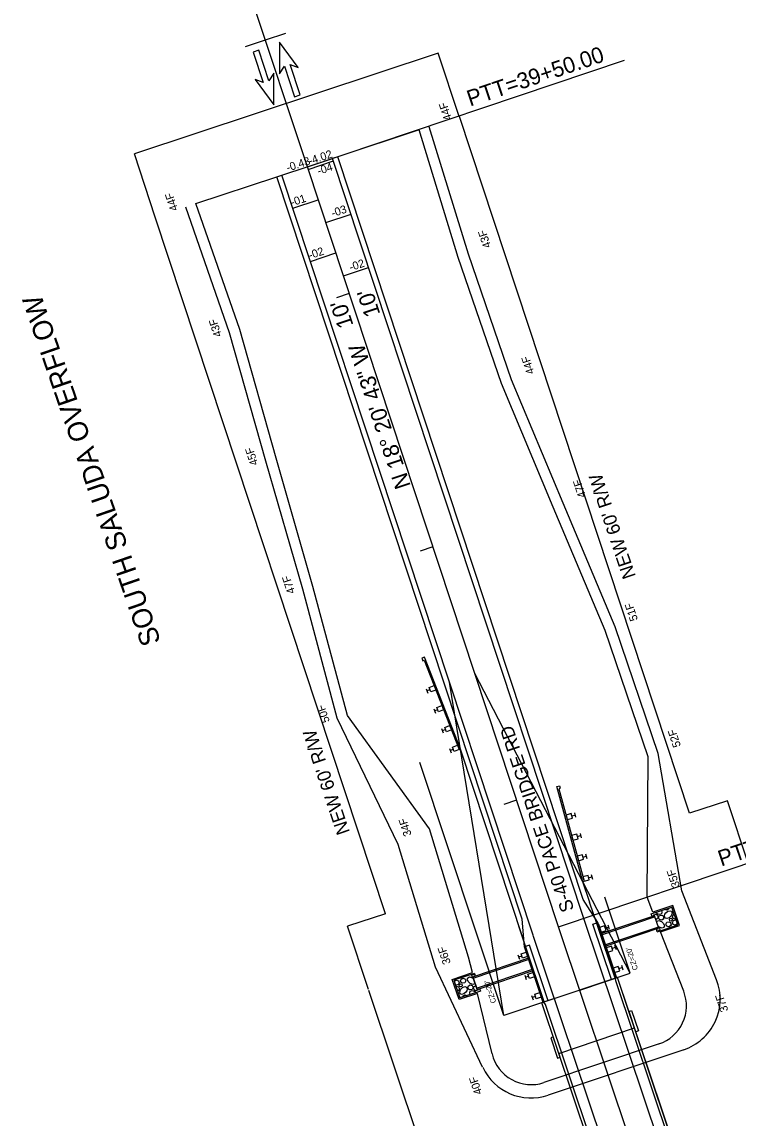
# Model space of a CAD drawing. Extents: x 1528853 to 1624411, y 1119753 to 1162242.
# Drawn here: x 1529299.1 to 1529567.4, y 1160646.7 to 1161057.5 of the extents above; entities that cross this region are included whole.
import ezdxf

# ---------------------------------------------------------------- set-up
doc = ezdxf.new("R2010")
doc.units = 0
for name, color, linetype in [('BR_CONCRETE', 7, 'Continuous'), ('Drainage-Trench', 7, 'Continuous'), ('RD_EX_Road Text', 7, 'Continuous'), ('RD_HC_Cl', 7, 'Continuous'), ('RD_HC_Data', 7, 'Continuous'), ('RD_HC_Data_Tic', 7, 'Continuous'), ('RD_PD_ALT1_TX', 7, 'Continuous'), ('RD_PD_BOC', 7, 'Continuous'), ('RD_PD_CstnLmt', 7, 'Continuous'), ('RD_PD_CstnLmt_TX', 7, 'Continuous'), ('RD_PD_DR_ErosCtrl', 7, 'Continuous'), ('RD_PD_DR_Inlet', 7, 'Continuous'), ('RD_PD_Final_TrvlWay', 7, 'Continuous'), ('RD_PD_Final_TX', 7, 'Continuous'), ('RD_PD_GR', 7, 'Continuous'), ('RD_PD_PaveDit', 7, 'Continuous'), ('RD_PD_PaveShd', 7, 'Continuous'), ('RD_PD_RW', 7, 'Continuous'), ('RD_Sketch8', 7, 'Continuous'), ('RD_TX_Pipe_ElevEX', 7, 'Continuous')]:
    doc.layers.add(name, color=color, linetype=linetype)

# ---------------------------------------------------------------- blocks, each defined once
blk = doc.blocks.new('Guardrail_MTBBC2_Transition')
at = {"layer": 'RD_PD_GR'}
for p, q in [((0, 0.5), (0, 0)), ((21.25, 0.5), (0, 0.5)), ((0, 0), (21.25, 0)), ((3.875, 3.75), (2.125, 3.75)), ((2.125, 0.5), (2.125, 2.5)), ((2.125, 2.5), (3.875, 2.5)), ((3.875, 0.5), (2.125, 0.5)), ((3, 2.5), (3, 3.75)), ((3.875, 2.5), (3.875, 0.5)), ((11.875, 3.75), (10.125, 3.75)), ((10.125, 0.5), (10.125, 2.5)), ((10.125, 2.5), (11.875, 2.5)), ((11.875, 0.5), (10.125, 0.5)), ((11, 2.5), (11, 3.75)), ((11.875, 2.5), (11.875, 0.5)), ((15, 0.5), (15, 0)), ((19.875, 3.75), (18.125, 3.75)), ((18.125, 0.5), (18.125, 2.5)), ((18.125, 2.5), (19.875, 2.5)), ((19.875, 0.5), (18.125, 0.5)), ((19, 2.5), (19, 3.75)), ((19.875, 2.5), (19.875, 0.5)), ((21.25, 0), (21.25, 0.5))]:
    blk.add_line(p, q, dxfattribs=at)

msp = doc.modelspace()

# ---------------------------------------------------------------- linework, layer by layer
at = {"layer": 'BR_CONCRETE'}
for p, q in [((1529522.3, 1160699.42), (1529493.86, 1160689.87)), ((1529521.59, 1160698.13), (1529521.51, 1160699.15)), ((1529559.16, 1160586.27), (1529521.59, 1160698.13)), ((1529560.43, 1160585.64), (1529522.22, 1160699.39)), ((1529560.51, 1160585.66), (1529522.3, 1160699.42)), ((1529532.07, 1160576.11), (1529493.86, 1160689.87)), ((1529532.15, 1160576.14), (1529493.94, 1160689.89)), ((1529495.2, 1160689.26), (1529494.65, 1160690.13)), ((1529532.78, 1160577.4), (1529495.2, 1160689.26)), ((1529500.23, 1160670.91), (1529528.66, 1160680.46))]:
    msp.add_line(p, q, dxfattribs=at)
for points in [[(1529530.09, 1160679.36), (1529529.14, 1160679.04), (1529526.6, 1160686.62), (1529527.54, 1160686.94)], [(1529499.76, 1160669.17), (1529500.7, 1160669.48), (1529498.16, 1160677.07), (1529497.21, 1160676.75)]]:
    msp.add_lwpolyline(points, close=True, dxfattribs=at)
at = {"layer": 'Drainage-Trench'}
for p, q in [((1529534.9, 1160723.17), (1529542.59, 1160725.75)), ((1529535.22, 1160722.22), (1529534.9, 1160723.17)), ((1529537.76, 1160717.8), (1529536.16, 1160722.54)), ((1529544.82, 1160719.12), (1529542.59, 1160725.75)), ((1529537.13, 1160716.53), (1529544.82, 1160719.12)), ((1529537.13, 1160716.53), (1529536.81, 1160717.48)), ((1529468.64, 1160700.91), (1529460.94, 1160698.32)), ((1529460.94, 1160698.32), (1529463.17, 1160691.69)), ((1529468.01, 1160699.64), (1529469.6, 1160694.9)), ((1529468.64, 1160700.91), (1529468.96, 1160699.96)), ((1529470.87, 1160694.27), (1529463.17, 1160691.69)), ((1529470.55, 1160695.22), (1529470.87, 1160694.27))]:
    msp.add_line(p, q, dxfattribs=at)
at = {"layer": 'RD_HC_Cl'}
for p, q in [((1529406.02, 1161003.2), (1529346.24, 1161183.48)), ((1529500.12, 1160718.34), (1529406.02, 1161003.2)), ((1529913.5, 1159487.74), (1529500.12, 1160718.34))]:
    msp.add_line(p, q, dxfattribs=at)
at = {"layer": 'RD_HC_Data'}
for p, q in [((1529406.02, 1161003.2), (1529524.92, 1161043.14)), ((1529500.12, 1160718.34), (1529619.02, 1160758.28))]:
    msp.add_line(p, q, dxfattribs=at)
at = {"layer": 'RD_HC_Data_Tic'}
for p, q in [((1529390.28, 1161050.66), (1529382.68, 1161048.14)), ((1529397.87, 1161053.18), (1529390.28, 1161050.66)), ((1529421.7, 1160955.72), (1529416.95, 1160954.16)), ((1529453.07, 1160860.77), (1529448.32, 1160859.2)), ((1529484.43, 1160765.82), (1529479.69, 1160764.25))]:
    msp.add_line(p, q, dxfattribs=at)
at = {"layer": 'RD_PD_ALT1_TX'}
for p, q in [((1529406.33, 1161002.25), (1529415.82, 1161005.4)), ((1529400.6, 1160987.71), (1529410.11, 1160990.86)), ((1529412.94, 1160982.32), (1529422.41, 1160985.46)), ((1529407.19, 1160967.77), (1529416.72, 1160970.93)), ((1529419.55, 1160962.39), (1529428.99, 1160965.52))]:
    msp.add_line(p, q, dxfattribs=at)
at = {"layer": 'RD_PD_BOC'}
for p, q in [((1529512.96, 1160719.36), (1529514.86, 1160719.99)), ((1529519.94, 1160698.58), (1529512.96, 1160719.35)), ((1529521.84, 1160699.22), (1529514.86, 1160719.99)), ((1529489.25, 1160711.44), (1529487.35, 1160710.8)), ((1529494.33, 1160690.03), (1529487.35, 1160710.8)), ((1529496.23, 1160690.66), (1529489.25, 1160711.44))]:
    msp.add_line(p, q, dxfattribs=at)
at = {"layer": 'RD_PD_CstnLmt'}
for p, q in [((1529447.9, 1161017.04), (1529417.41, 1161006.96)), ((1529462.57, 1160969.23), (1529447.9, 1161017.04)), ((1529364.28, 1160989.41), (1529394.62, 1160999.44)), ((1529380.7, 1160942.18), (1529364.28, 1160989.41)), ((1529478.82, 1160921.94), (1529462.57, 1160969.23)), ((1529394.3, 1160894.01), (1529380.7, 1160942.18)), ((1529498.15, 1160875.67), (1529478.82, 1160921.94)), ((1529408.14, 1160845.93), (1529394.3, 1160894.01)), ((1529517.58, 1160829.42), (1529498.15, 1160875.67)), ((1529421.11, 1160797.56), (1529408.14, 1160845.93)), ((1529533.7, 1160782.09), (1529517.58, 1160829.42)), ((1529451.8, 1160755.04), (1529421.11, 1160797.56)), ((1529533.33, 1160729.5), (1529533.7, 1160782.09)), ((1529466.45, 1160707.03), (1529451.8, 1160755.04)), ((1529535.51, 1160723.9), (1529533.33, 1160729.5)), ((1529542.91, 1160726.39), (1529535.51, 1160723.9)), ((1529545.46, 1160718.8), (1529542.91, 1160726.39)), ((1529538.41, 1160716.44), (1529545.46, 1160718.8)), ((1529547.05, 1160694.24), (1529538.41, 1160716.44)), ((1529467.86, 1160701.18), (1529466.45, 1160707.03)), ((1529460.31, 1160698.64), (1529467.86, 1160701.18)), ((1529462.85, 1160691.06), (1529460.31, 1160698.64)), ((1529469.75, 1160693.37), (1529462.85, 1160691.06)), ((1529475.22, 1160670.74), (1529469.75, 1160693.37)), ((1529537.79, 1160674.46), (1529494.69, 1160659.98))]:
    msp.add_line(p, q, dxfattribs=at)
for centre, start, end in [((1529532.98, 1160688.77), 288.568, 21.2575), ((1529489.89, 1160674.29), 193.5876, 288.568)]:
    msp.add_arc(centre, 15.09, start, end, dxfattribs=at)
at = {"layer": 'RD_PD_DR_ErosCtrl'}
for p, q in [((1529466.38, 1160970.46), (1529451.73, 1161018.21)), ((1529376.88, 1160940.98), (1529360.5, 1160988.1)), ((1529482.56, 1160923.36), (1529466.38, 1160970.46)), ((1529390.45, 1160892.92), (1529376.88, 1160940.98)), ((1529501.84, 1160877.21), (1529482.56, 1160923.36)), ((1529404.28, 1160844.86), (1529390.45, 1160892.92)), ((1529521.32, 1160830.85), (1529501.84, 1160877.21)), ((1529417.25, 1160796.52), (1529404.28, 1160844.86)), ((1529537.49, 1160783.38), (1529521.32, 1160830.85)), ((1529440, 1160749.18), (1529417.25, 1160796.52)), ((1529546.35, 1160731.89), (1529537.49, 1160783.38)), ((1529454.01, 1160703.24), (1529440, 1160749.18)), ((1529559.34, 1160698.51), (1529546.35, 1160731.89)), ((1529471.71, 1160665.72), (1529454.01, 1160703.24)), ((1529547.06, 1160672.3), (1529496.29, 1160655.24))]:
    msp.add_line(p, q, dxfattribs=at)
for centre, radius, start, end in [((1529540.7, 1160691.26), 20, 288.568, 21.2575), ((1529489.89, 1160674.29), 20.09, 205.2589, 288.568)]:
    msp.add_arc(centre, radius, start, end, dxfattribs=at)
at = {"layer": 'RD_PD_DR_Inlet'}
for p, q in [((1529536.16, 1160722.54), (1529515.91, 1160715.73)), ((1529536.32, 1160722.06), (1529516.07, 1160715.26)), ((1529537.76, 1160717.8), (1529536.16, 1160722.54)), ((1529537.6, 1160718.27), (1529517.34, 1160711.47)), ((1529537.76, 1160717.8), (1529517.5, 1160710.99)), ((1529468.01, 1160699.64), (1529489.38, 1160706.82)), ((1529468.17, 1160699.17), (1529489.54, 1160706.35)), ((1529469.44, 1160695.38), (1529490.81, 1160702.56)), ((1529469.6, 1160694.9), (1529490.97, 1160702.08)), ((1529469.6, 1160694.9), (1529468.01, 1160699.64))]:
    msp.add_line(p, q, dxfattribs=at)
at = {"layer": 'RD_PD_Final_TrvlWay'}
for p, q in [((1529396.52, 1161000.05), (1529415.51, 1161006.35)), ((1529509.61, 1160721.48), (1529415.51, 1161006.34)), ((1529490.62, 1160715.2), (1529396.52, 1161000.06)), ((1529628.69, 1160366.99), (1529509.6, 1160721.52)), ((1529609.73, 1160360.62), (1529490.64, 1160715.16))]:
    msp.add_line(p, q, dxfattribs=at)
at = {"layer": 'RD_PD_Final_TX'}
for p, q in [((1529387.88, 1161046.89), (1529385.74, 1161046.18)), ((1529391.64, 1161035.49), (1529387.88, 1161046.89)), ((1529402.63, 1161040.42), (1529395.61, 1161049.95)), ((1529395.61, 1161049.95), (1529395.65, 1161038.11)), ((1529385.74, 1161046.18), (1529389.51, 1161034.79)), ((1529393.41, 1161038.29), (1529391.64, 1161035.49)), ((1529393.45, 1161026.45), (1529393.41, 1161038.29)), ((1529395.65, 1161038.11), (1529397.41, 1161040.91)), ((1529397.41, 1161040.91), (1529401.18, 1161029.51)), ((1529403.31, 1161030.22), (1529399.55, 1161041.61)), ((1529399.55, 1161041.61), (1529402.63, 1161040.42)), ((1529386.43, 1161035.98), (1529393.45, 1161026.45)), ((1529389.51, 1161034.79), (1529386.43, 1161035.98)), ((1529401.18, 1161029.51), (1529403.31, 1161030.22))]:
    msp.add_line(p, q, dxfattribs=at)
at = {"layer": 'RD_PD_GR'}
for p, q in [((1529449.88, 1160819.41), (1529448.95, 1160819.04)), ((1529448.95, 1160819.04), (1529449.32, 1160818.11)), ((1529449.32, 1160818.11), (1529449.78, 1160818.29)), ((1529449.78, 1160818.29), (1529462.9, 1160784.77)), ((1529463.37, 1160784.95), (1529449.88, 1160819.41)), ((1529451.06, 1160815.03), (1529451.52, 1160815.21)), ((1529451.66, 1160808.02), (1529453.52, 1160808.75)), ((1529453.52, 1160808.75), (1529454.16, 1160807.12)), ((1529450.49, 1160807.56), (1529451.13, 1160805.93)), ((1529451.97, 1160807.2), (1529450.81, 1160806.75)), ((1529452.29, 1160806.39), (1529451.66, 1160808.02)), ((1529454.16, 1160807.12), (1529452.29, 1160806.39)), ((1529453.41, 1160800.11), (1529454.04, 1160798.48)), ((1529454.57, 1160800.57), (1529456.43, 1160801.3)), ((1529455.21, 1160798.94), (1529454.57, 1160800.57)), ((1529456.43, 1160801.3), (1529457.07, 1160799.67)), ((1529454.89, 1160799.75), (1529453.73, 1160799.3)), ((1529457.07, 1160799.67), (1529455.21, 1160798.94)), ((1529456.32, 1160792.66), (1529456.96, 1160791.03)), ((1529457.81, 1160792.3), (1529456.64, 1160791.85)), ((1529457.49, 1160793.12), (1529459.35, 1160793.85)), ((1529458.12, 1160791.49), (1529457.49, 1160793.12)), ((1529459.99, 1160792.22), (1529458.12, 1160791.49)), ((1529459.35, 1160793.85), (1529459.99, 1160792.22)), ((1529459.24, 1160785.21), (1529459.88, 1160783.58)), ((1529460.72, 1160784.85), (1529459.56, 1160784.4)), ((1529460.4, 1160785.67), (1529462.27, 1160786.4)), ((1529461.04, 1160784.04), (1529460.4, 1160785.67)), ((1529462.9, 1160784.77), (1529461.04, 1160784.04)), ((1529462.27, 1160786.4), (1529462.9, 1160784.77)), ((1529462.9, 1160784.77), (1529463.37, 1160784.95)), ((1529486.85, 1160713.88), (1529463.37, 1160784.95)), ((1529499.51, 1160770.98), (1529500.47, 1160771.24)), ((1529500.47, 1160771.24), (1529500.73, 1160770.27)), ((1529509.24, 1160735.28), (1529499.51, 1160770.98)), ((1529500.73, 1160770.27), (1529500.25, 1160770.14)), ((1529500.25, 1160770.14), (1529509.72, 1160735.41)), ((1529501.17, 1160766.77), (1529500.69, 1160766.63)), ((1529504.88, 1160760.78), (1529502.95, 1160760.25)), ((1529502.95, 1160760.25), (1529503.41, 1160758.57)), ((1529503.41, 1160758.57), (1529505.34, 1160759.09)), ((1529505.34, 1160759.09), (1529504.88, 1160760.78)), ((1529505.11, 1160759.94), (1529506.31, 1160760.26)), ((1529506.08, 1160761.11), (1529506.54, 1160759.42)), ((1529506.98, 1160753.06), (1529505.05, 1160752.54)), ((1529505.05, 1160752.54), (1529505.51, 1160750.85)), ((1529505.51, 1160750.85), (1529507.44, 1160751.37)), ((1529507.44, 1160751.37), (1529506.98, 1160753.06)), ((1529507.21, 1160752.22), (1529508.42, 1160752.55)), ((1529508.19, 1160753.39), (1529508.65, 1160751.7)), ((1529509.09, 1160745.34), (1529507.16, 1160744.82)), ((1529507.16, 1160744.82), (1529507.62, 1160743.13)), ((1529507.62, 1160743.13), (1529509.55, 1160743.66)), ((1529509.55, 1160743.66), (1529509.09, 1160745.34)), ((1529509.32, 1160744.5), (1529510.52, 1160744.83)), ((1529510.29, 1160745.67), (1529510.75, 1160743.98)), ((1529509.72, 1160735.41), (1529509.24, 1160735.28)), ((1529511.82, 1160727.47), (1529509.24, 1160735.28)), ((1529511.19, 1160737.63), (1529509.26, 1160737.1)), ((1529509.26, 1160737.1), (1529509.72, 1160735.41)), ((1529509.72, 1160735.41), (1529511.65, 1160735.94)), ((1529511.65, 1160735.94), (1529511.19, 1160737.63)), ((1529511.42, 1160736.78), (1529512.63, 1160737.11)), ((1529512.4, 1160737.95), (1529512.86, 1160736.27)), ((1529514.6, 1160719.2), (1529511.8, 1160727.54)), ((1529488.04, 1160710.33), (1529485.27, 1160718.58))]:
    msp.add_line(p, q, dxfattribs=at)
at = {"layer": 'RD_PD_PaveDit'}
for p, q in [((1529536.82, 1160723.45), (1529536.58, 1160723.73)), ((1529540.71, 1160724.63), (1529539.94, 1160724.86)), ((1529536.69, 1160721.16), (1529536.62, 1160721.18)), ((1529537.73, 1160718.35), (1529537.47, 1160718.66)), ((1529468.04, 1160699.09), (1529468.3, 1160698.78)), ((1529468.95, 1160693.99), (1529469.18, 1160693.71)), ((1529469.08, 1160696.28), (1529469.14, 1160696.27)), ((1529465.06, 1160692.81), (1529465.82, 1160692.58))]:
    msp.add_line(p, q, dxfattribs=at)
for points in [[(1529535.66, 1160722.37), (1529535.92, 1160722.87), (1529536.72, 1160723.05), (1529537.27, 1160722.71), (1529537.46, 1160721.94), (1529537.24, 1160721.47), (1529536.69, 1160721.16)], [(1529538.68, 1160724.44), (1529538.9, 1160723.84), (1529538.71, 1160723.24), (1529538.04, 1160722.96), (1529537.29, 1160723.15), (1529536.78, 1160723.48)], [(1529538.79, 1160720.86), (1529537.95, 1160721.11), (1529537.65, 1160721.86), (1529538.02, 1160722.57), (1529538.82, 1160722.76), (1529539.37, 1160722.42), (1529539.57, 1160721.65), (1529539.34, 1160721.18), (1529538.79, 1160720.86)], [(1529540.32, 1160723.55), (1529541.09, 1160724.2), (1529541.94, 1160724.41), (1529542.45, 1160724.17), (1529542.67, 1160723.5), (1529542.33, 1160722.54), (1529541.57, 1160721.78), (1529540.71, 1160721.47), (1529540.11, 1160721.65), (1529539.83, 1160722.32), (1529540.02, 1160723.07), (1529540.35, 1160723.58)], [(1529541.46, 1160725.37), (1529541.26, 1160724.95), (1529540.71, 1160724.63)], [(1529542.79, 1160725.18), (1529542.58, 1160725.42), (1529542.51, 1160725.72)], [(1529543.93, 1160721.28), (1529543.09, 1160721.52), (1529542.79, 1160722.27), (1529543.16, 1160722.99), (1529543.5, 1160723.07)], [(1529536.96, 1160720.17), (1529537.11, 1160720.49), (1529537.78, 1160720.7), (1529538.73, 1160720.36), (1529539.5, 1160719.6), (1529539.8, 1160718.74), (1529539.62, 1160718.14), (1529538.95, 1160717.86), (1529538.2, 1160718.05), (1529537.69, 1160718.38)], [(1529537.67, 1160718.06), (1529537.97, 1160717.87), (1529538.09, 1160717.41), (1529537.95, 1160717.13), (1529537.62, 1160716.94)], [(1529541.52, 1160718.37), (1529540.68, 1160718.62), (1529540.38, 1160719.37), (1529540.76, 1160720.08), (1529541.55, 1160720.26), (1529542.1, 1160719.93), (1529542.3, 1160719.15), (1529542.08, 1160718.68), (1529541.52, 1160718.37)], [(1529542.37, 1160720.48), (1529541.86, 1160720.63), (1529541.68, 1160721.08), (1529541.9, 1160721.51), (1529542.38, 1160721.62), (1529542.71, 1160721.41), (1529542.83, 1160720.95), (1529542.7, 1160720.67), (1529542.37, 1160720.48)], [(1529543.93, 1160719.03), (1529543.09, 1160719.28), (1529542.79, 1160720.03), (1529543.16, 1160720.74), (1529543.96, 1160720.92), (1529544.28, 1160720.72)], [(1529544.07, 1160721.36), (1529543.93, 1160721.28)], [(1529544.64, 1160719.67), (1529544.48, 1160719.34), (1529543.93, 1160719.03)], [(1529537.62, 1160716.94), (1529537.11, 1160717.09), (1529536.94, 1160717.52)], [(1529461.13, 1160697.77), (1529461.28, 1160698.1), (1529461.83, 1160698.41)], [(1529461.83, 1160698.41), (1529462.67, 1160698.16), (1529462.97, 1160697.41), (1529462.6, 1160696.7), (1529461.81, 1160696.52), (1529461.48, 1160696.72)], [(1529464.24, 1160699.07), (1529465.08, 1160698.82), (1529465.38, 1160698.07), (1529465.01, 1160697.36), (1529464.21, 1160697.18), (1529463.66, 1160697.52), (1529463.46, 1160698.29), (1529463.69, 1160698.76), (1529464.24, 1160699.07)], [(1529468.81, 1160697.27), (1529468.66, 1160696.95), (1529467.99, 1160696.74), (1529467.03, 1160697.08), (1529466.27, 1160697.84), (1529465.96, 1160698.7), (1529466.14, 1160699.3), (1529466.81, 1160699.58), (1529467.56, 1160699.39), (1529468.07, 1160699.06)], [(1529468.09, 1160699.39), (1529467.8, 1160699.57), (1529467.68, 1160700.03), (1529467.81, 1160700.31), (1529468.15, 1160700.5)], [(1529468.15, 1160700.5), (1529468.65, 1160700.35), (1529468.82, 1160699.92)], [(1529461.69, 1160696.08), (1529461.84, 1160696.17)], [(1529461.84, 1160696.17), (1529462.68, 1160695.92), (1529462.98, 1160695.17), (1529462.61, 1160694.45), (1529462.27, 1160694.38)], [(1529463.4, 1160696.96), (1529463.9, 1160696.81), (1529464.08, 1160696.36), (1529463.86, 1160695.93), (1529463.38, 1160695.82), (1529463.05, 1160696.03), (1529462.93, 1160696.49), (1529463.07, 1160696.77), (1529463.4, 1160696.96)], [(1529465.45, 1160693.89), (1529464.67, 1160693.24), (1529463.82, 1160693.03), (1529463.31, 1160693.27), (1529463.1, 1160693.94), (1529463.44, 1160694.9), (1529464.2, 1160695.67), (1529465.06, 1160695.97), (1529465.66, 1160695.79), (1529465.93, 1160695.12), (1529465.75, 1160694.37), (1529465.42, 1160693.86)], [(1529466.98, 1160696.58), (1529467.82, 1160696.33), (1529468.12, 1160695.58), (1529467.74, 1160694.87), (1529466.95, 1160694.68), (1529466.4, 1160695.02), (1529466.2, 1160695.8), (1529466.42, 1160696.27), (1529466.98, 1160696.58)], [(1529467.08, 1160693), (1529466.87, 1160693.6), (1529467.05, 1160694.2), (1529467.72, 1160694.48), (1529468.47, 1160694.29), (1529468.98, 1160693.96)], [(1529470.11, 1160695.07), (1529469.84, 1160694.57), (1529469.05, 1160694.39), (1529468.5, 1160694.73), (1529468.3, 1160695.5), (1529468.52, 1160695.97), (1529469.08, 1160696.28)], [(1529462.98, 1160692.26), (1529463.18, 1160692.02), (1529463.25, 1160691.72)], [(1529464.3, 1160692.07), (1529464.5, 1160692.49), (1529465.06, 1160692.81)]]:
    msp.add_lwpolyline(points, dxfattribs=at)
at = {"layer": 'RD_PD_PaveShd'}
for p, q in [((1529417.4, 1161006.98), (1529415.51, 1161006.35)), ((1529509.38, 1160728.57), (1529417.41, 1161006.96)), ((1529394.62, 1160999.42), (1529396.52, 1161000.05)), ((1529486.53, 1160721.21), (1529394.62, 1160999.44)), ((1529514.86, 1160719.99), (1529509.38, 1160728.57)), ((1529487.35, 1160710.8), (1529486.53, 1160721.21))]:
    msp.add_line(p, q, dxfattribs=at)
at = {"layer": 'RD_PD_RW'}
for p, q in [((1529455.1, 1161045.81), (1529341.2, 1161008.04)), ((1529462.97, 1161022.08), (1529455.1, 1161045.81)), ((1529549.25, 1160760.9), (1529462.99, 1161022.02)), ((1529349.06, 1160984.32), (1529341.2, 1161008.04)), ((1529435.3, 1160723.26), (1529349.04, 1160984.38)), ((1529563.49, 1160765.6), (1529549.25, 1160760.9)), ((1529571.33, 1160741.87), (1529563.49, 1160765.6)), ((1529435.3, 1160723.26), (1529421.06, 1160718.55)), ((1529428.9, 1160694.82), (1529421.06, 1160718.55)), ((1529715.61, 1159841.31), (1529429.02, 1160694.46))]:
    msp.add_line(p, q, dxfattribs=at)
at = {"layer": 'RD_Sketch8'}
for p, q in [((1529527.04, 1160701.01), (1529468.75, 1160813.3)), ((1529479.64, 1160685.09), (1529459.27, 1160810.11)), ((1529479.64, 1160685.09), (1529448.16, 1160780.01)), ((1529479.64, 1160685.09), (1529448.16, 1160780.01)), ((1529527.04, 1160701.01), (1529517.48, 1160729.45)), ((1529508.08, 1160694.64), (1529527.04, 1160701.01)), ((1529498.6, 1160691.46), (1529479.64, 1160685.09))]:
    msp.add_line(p, q, dxfattribs=at)

# ---------------------------------------------------------------- block references
at = {"layer": 'RD_PD_BOC', "yscale": -0.9999999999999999, "rotation": 108.56800570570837}
msp.add_blockref('Guardrail_MTBBC2_Transition', (1529521.36, 1160699.06), dxfattribs=at)
at = {"layer": 'RD_PD_BOC', "rotation": 108.5680057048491}
msp.add_blockref('Guardrail_MTBBC2_Transition', (1529494.81, 1160690.19), dxfattribs=at)

# ---------------------------------------------------------------- texts
at = {"layer": 'RD_EX_Road Text'}
msp.add_text('S-40 PACE BRIDGE RD', height=5, rotation=108.5527, dxfattribs=at).set_placement((1529506.06, 1160724.86))
at = {"layer": 'RD_HC_Data'}
for s, height, rotation, p in [('PTT=39+50.00', 6, 18.568, (1529466.99, 1161025.79)), ('SOUTH SALUDA OVERFLOW', 7.5, 109.0239, (1529351.21, 1160825.2)), ('N 18%%d 20\' 43" W', 6, 108.3453, (1529444.84, 1160883.64)), ('PTT=36+50.00', 6, 18.568, (1529561.1, 1160740.93))]:
    msp.add_text(s, height=height, rotation=rotation, dxfattribs=at).set_placement(p)
at = {"layer": 'RD_PD_ALT1_TX'}
for s, rotation, p in [('-04', 18.3453, (1529410.31, 1161000.14)), ('-01', 18.3453, (1529400.31, 1160988.38)), ('-03', 18.3453, (1529415.54, 1160984.32)), ('-02', 18.5527, (1529407.03, 1160968.56)), ('-02', 18.3453, (1529422.26, 1160964.07))]:
    msp.add_text(s, height=3, rotation=rotation, dxfattribs=at).set_placement(p)
at = {"layer": 'RD_PD_CstnLmt_TX'}
for s, rotation, p in [('44F', 108.2806, (1529460.25, 1161021.12)), ('44F', 108.2806, (1529357.63, 1160987.22)), ('43F', 108.2806, (1529474.92, 1160973.3)), ('43F', 108.2806, (1529374.05, 1160939.98)), ('44F', 108.2806, (1529491.17, 1160926.01)), ('45F', 108.2806, (1529387.65, 1160891.82)), ('47F', 108.2806, (1529510.5, 1160879.74)), ('47F', 108.2806, (1529401.49, 1160843.73)), ('51F', 108.2806, (1529529.92, 1160833.5)), ('50F', 108.2806, (1529414.46, 1160795.36)), ('52F', 108.2806, (1529546.04, 1160786.17)), ('34F', 108.2806, (1529445.16, 1160752.84)), ('35F', 108.568, (1529545.65, 1160733.64)), ('36F', 108.568, (1529459.81, 1160704.8)), ('37F', 108.568, (1529563.8, 1160686.99)), ('40F', 108.568, (1529471.6, 1160656.02))]:
    msp.add_text(s, height=3, rotation=rotation, dxfattribs=at).set_placement(p)
at = {"layer": 'RD_PD_Final_TX'}
for p in [(1529433.44, 1160948.07), (1529423.39, 1160943.85)]:
    msp.add_text("10'", height=6, rotation=108.2813, dxfattribs=at).set_placement(p)
at = {"layer": 'RD_PD_RW'}
for p in [(1529529.17, 1160849.78), (1529422.02, 1160753.87)]:
    msp.add_text("NEW 60' R/W", height=5, rotation=108.5527, dxfattribs=at).set_placement(p)
at = {"layer": 'RD_Sketch8'}
for p in [(1529529.98, 1160702.47), (1529476.84, 1160690.08)]:
    msp.add_text("CZ=20'", height=2, rotation=108.3453, dxfattribs=at).set_placement(p)
at = {"layer": 'RD_TX_Pipe_ElevEX'}
for s, p in [('-4.02', (1529407, 1161003.91)), ('-0.43', (1529398.69, 1161001.35))]:
    msp.add_text(s, height=3, rotation=18.3453, dxfattribs=at).set_placement(p)

doc.saveas('drawing.dxf')
